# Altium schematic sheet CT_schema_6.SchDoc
size 391 x 238 mm
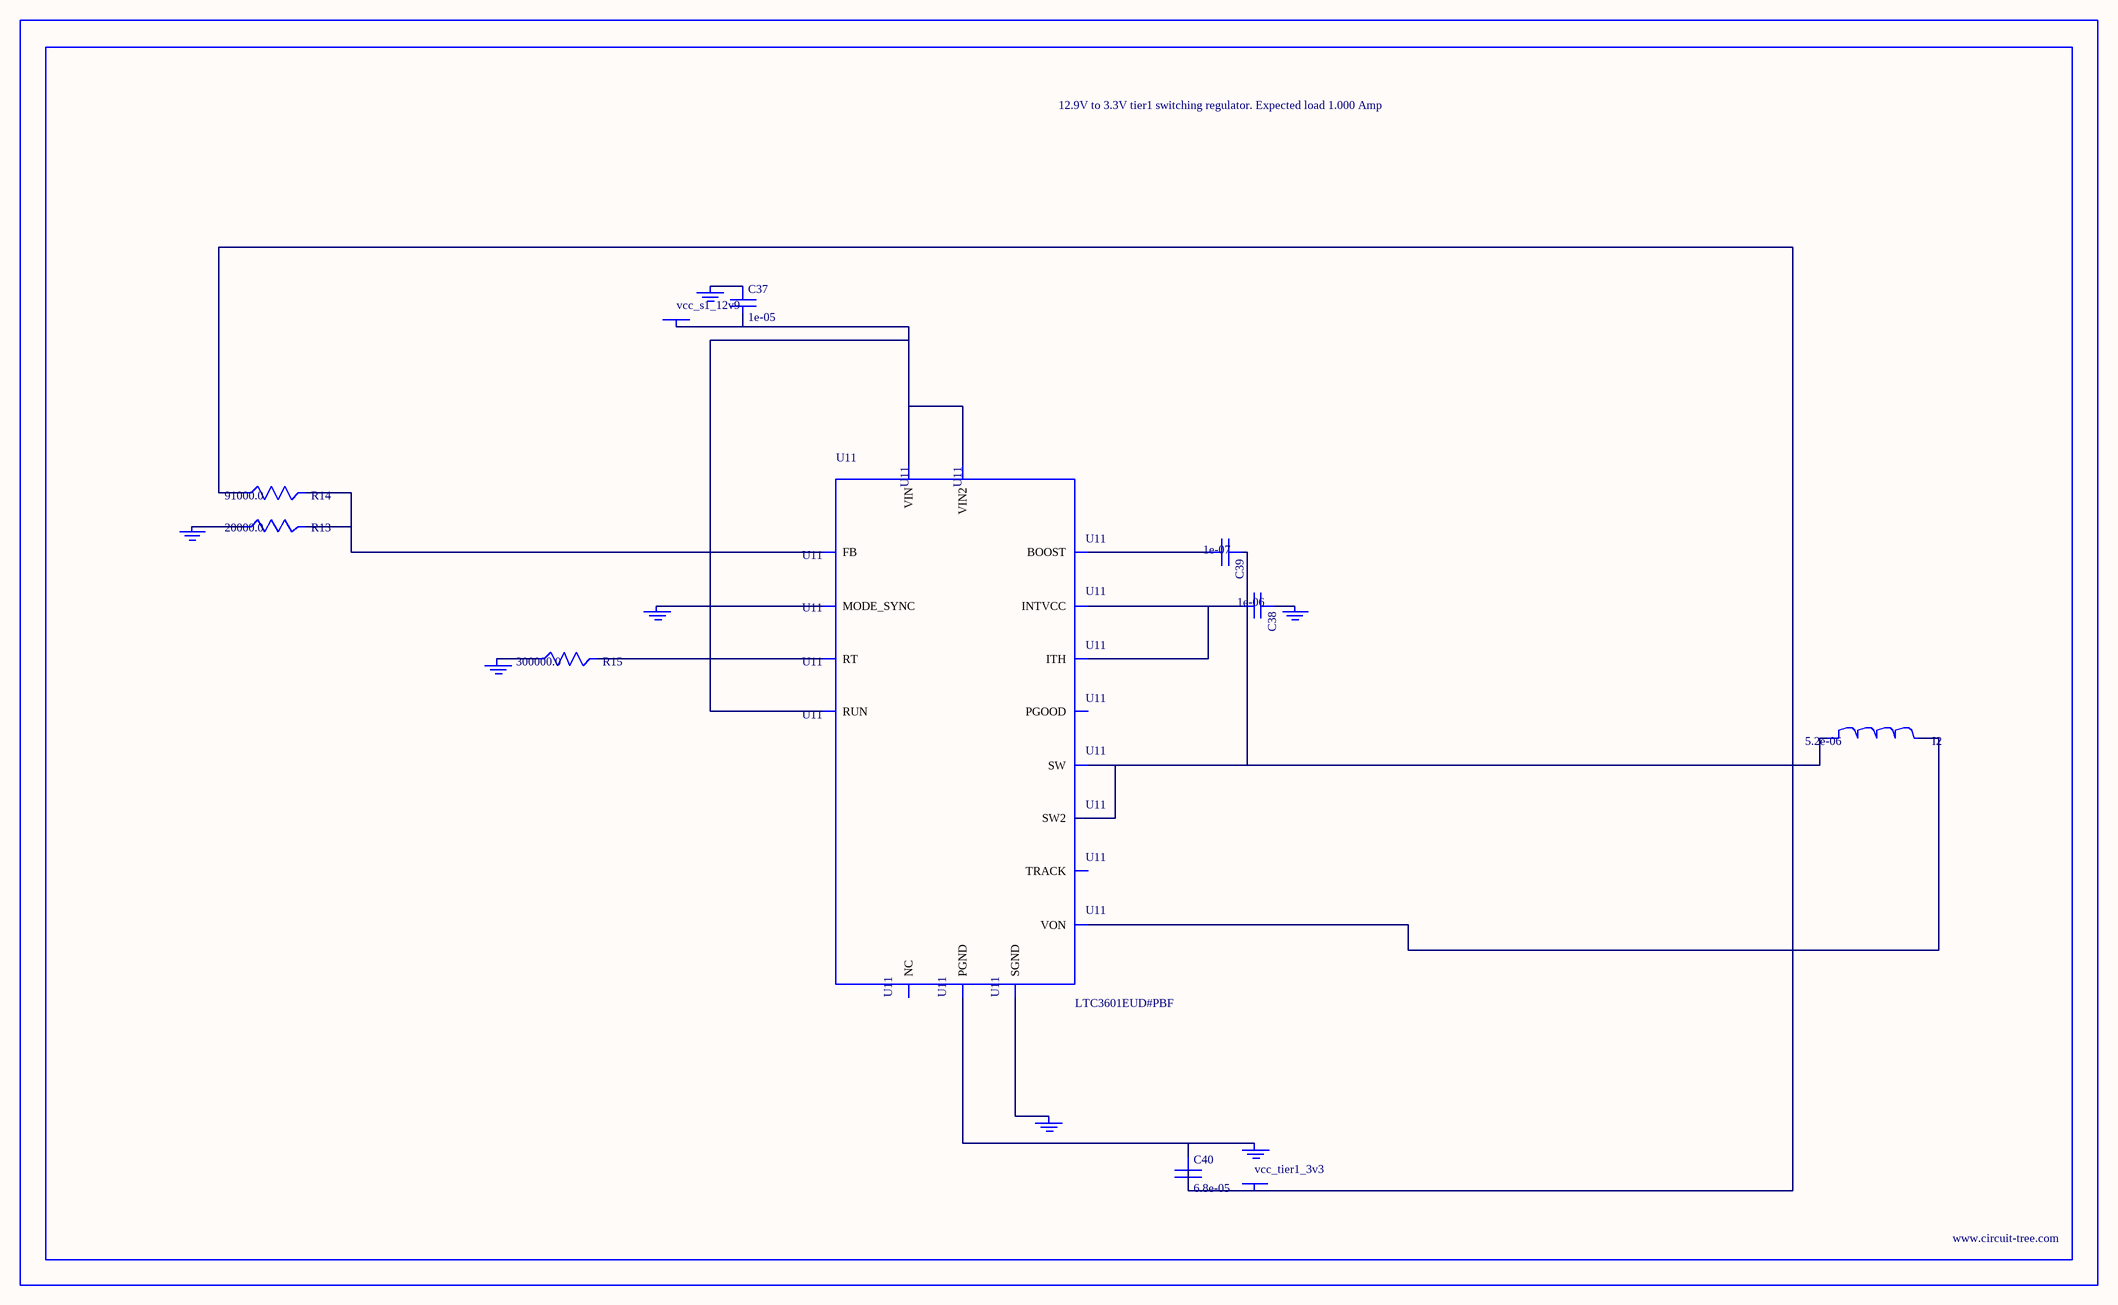
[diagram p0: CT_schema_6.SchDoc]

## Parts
BORDER5  (no value)
C37  1e-05  [C0805]
C38  1e-06  [C0603]
C39  1e-07  [C0402]
C40  6.8e-05  [2220]
GND_INSTANCE_5_0  (no value)
GND_INSTANCE_5_1  (no value)
GND_INSTANCE_5_2  (no value)
GND_INSTANCE_5_3  (no value)
GND_INSTANCE_5_4  (no value)
GND_INSTANCE_5_5  (no value)
GND_INSTANCE_5_6  (no value)
I2  5.2e-06  [DR1040]
POWER_INSTANCE_5_0  vcc_s1_12v9
POWER_INSTANCE_5_1  vcc_tier1_3v3
R13  20000.0  [R0603]
R14  91000.0  [R0603]
R15  300000.0  [R0603]
U11  LTC3601EUD#PBF  [QFN-16_EP]

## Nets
NetC37_1: C37.1 GND_INSTANCE_5_5.0(GND)
NetC37_2: C37.2 POWER_INSTANCE_5_0.0(PWR) U11.14(RUN) U11.15(VIN) U11.16(VIN2)
NetC38_1: C38.1 GND_INSTANCE_5_1.0(GND)
NetC38_2: C38.2 U11.7(INTVCC) U11.12(ITH)
NetC39_1: C39.1 I2.1 U11.3(SW) U11.4(SW2)
NetC39_2: C39.2 U11.6(BOOST)
NetC40_1: C40.1 GND_INSTANCE_5_6.0(GND) U11.17(PGND)
NetC40_2: C40.2 I2.2 POWER_INSTANCE_5_1.0(PWR) R14.1 U11.8(VON)
NetGND_INSTANCE_5_0_0: GND_INSTANCE_5_0.0(GND) U11.1(MODE_SYNC)
NetGND_INSTANCE_5_2_0: GND_INSTANCE_5_2.0(GND) U11.9(SGND)
NetGND_INSTANCE_5_3_0: GND_INSTANCE_5_3.0(GND) R15.1
NetGND_INSTANCE_5_4_0: GND_INSTANCE_5_4.0(GND) R13.1
NetR13_2: R13.2 R14.2 U11.11(FB)
NetR15_2: R15.2 U11.10(RT)

Not connected (* = marked no-connect by the designer): U11 2(PGOOD) 5(NC) 13(TRACK)

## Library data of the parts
BORDER5 = BORDER_PAGE5
C37 = C0805C106K8RACTU
C38 = C0603C105K3RACTU
C39 = C0402C104K3RACTU
C40 = C5750X5R1A686M
GND_INSTANCE_5_0-GND_INSTANCE_5_6 = GND
I2 = DR1040-5R2-R
POWER_INSTANCE_5_0 POWER_INSTANCE_5_1 = PWR
R13 = RC0603JR-0720KL
R14 = RC0603JR-0791KL
R15 = RC0603JR-07300KL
